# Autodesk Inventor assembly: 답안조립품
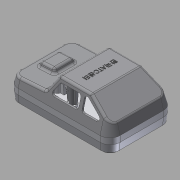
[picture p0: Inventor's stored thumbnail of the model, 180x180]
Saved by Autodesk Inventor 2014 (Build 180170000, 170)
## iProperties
Created: 2015-06
Part Number: 답안조립품
Document SubType Name: Assembly
Designer: Administrator
Author: Administrator
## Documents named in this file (7)
- C:\Documents and Settings\Administrator\바탕 화면\450508V1036\답안조립품.iam
- C:\Documents and Settings\Administrator\바탕 화면\450508V1036\본체.ipt
- C:\Documents and Settings\Administrator\바탕 화면\450508V1036\커버.ipt
- C:\Documents and Settings\Administrator\바탕 화면\450508V1036\M4x10.ipt
- C:\Documents and Settings\Administrator\바탕 화면\450508V1036\바퀴.ipt
- C:\Documents and Settings\Administrator\바탕 화면\450508V1036\바퀴고정부.ipt
- C:\Documents and Settings\Administrator\바탕 화면\450508V1036\M2x4.ipt
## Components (20 placed, 2 different names)
1. M4x10:1
2. M4x10:2
3. M4x10:3
4. M4x10:4
5. M2x4:1
6. M2x4:2
7. M2x4:3
8. M2x4:4
9. M2x4:5
10. M2x4:6
11. M2x4:7
12. M2x4:8
13. M2x4:9
14. M2x4:10
15. M2x4:11
16. M2x4:12
17. M2x4:13
18. M2x4:14
19. M2x4:15
20. M2x4:16
